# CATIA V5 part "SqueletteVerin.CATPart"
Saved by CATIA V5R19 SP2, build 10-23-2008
Part number: SqueletteVerin
Publications: "PointG", "AxeG", "Plane.2", "BodyVerin"
Bounding box of the stored display mesh (mm): x -51.935 to 0, y -48.787 to 81.213, z 0 to 183.212
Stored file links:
  D:\France\IFMA\IAO\Projet\SqueletteVerin.CATPart
  D:\France\IFMA\IAO\Projet\pruangdaja_CAO.CATProduct
  D:\France\IFMA\IAO\Projet\SquelettePrin.CATPart
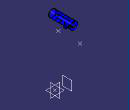
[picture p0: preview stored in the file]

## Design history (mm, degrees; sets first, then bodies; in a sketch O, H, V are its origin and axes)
External parameters (linked from other documents)
  External.Largeur = 10 mm
  External.RayonTrou = 5 mm
Set1
  Plane1: linked copy from another document
  Point1: linked copy from another document
  Point2: linked copy from another document
Set2
  Point3: (0, -70, 0), relative to Point2
  Line1: type PtDir, RefPoint Point3, Direction (1, 0, 0), Start -20, End 20
  Plane2: type Offset, RefPlane Plane1, Offset 40, reversed
  Sketch1 on Plane2, origin (-40, 0, 0), H (0, 1, 0), V (0, 0, 1)
    construction line L1 (11.2132, 171.2132) -> (-83.3873, 171.2132)
    line L2 (21.2132, 166.2132) -> (-33.7868, 166.2132)
    line L3 (-33.7868, 166.2132) -> (-33.7868, 171.2132)
    point P4 (-33.7868, 171.2132)
    line L4 (-33.7868, 171.2132) -> (-48.7868, 171.2132)
    line L5 (-48.7868, 171.2132) -> (-48.7868, 159.2132)
    line L6 (-48.7868, 159.2132) -> (21.2132, 159.2132)
    line L7 (21.2132, 159.2132) -> (21.2132, 166.2132)
    reference projected point E2 (11.2132, 171.2132) from Point3
    distance L2 L1 = 5 {= External.RayonTrou}
    length L5 = 12 {= Plane2.Offset /2 -8mm}
    distance L7 L5 = 70
    distance L3 L5 = 15
    distance L7 E2 = 10
    horizontal: L1 H, L2 H, L4 H, L6 H
    coincidence: P4 L1
    vertical: L3 V, L5 V, L7 V
Body1 (main body)
  Shaft1: profile Sketch1, axis Sketch1.L4, angle 360
  Sketch2 on Plane2, origin (-40, 0, 0), H (0, 1, 0), V (0, 0, 1)
    circle A1 centre (11.2132, 171.2132) radius 5
    point P1 (11.2132, 171.2132)
    reference projected point E1 (11.2132, 171.2132) from Point3
    radius A1 = 5 {= External.Largeur /2}
    coincidence: P1 E1
  Pad1: profile Sketch2, direction (1, 0, 0), length 18, opposite side length -8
